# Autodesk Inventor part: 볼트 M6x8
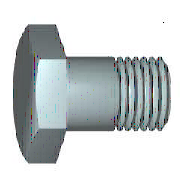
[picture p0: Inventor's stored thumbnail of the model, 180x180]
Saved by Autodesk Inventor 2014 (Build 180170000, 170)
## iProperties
Created: 2012-02
Part Number: 볼트 M6x8
Material: 강철, 연강
Description: 6각 머리 볼트 및 6각 머리 나사
Document SubType Name: Modeling
Standard: KS B 1002
Designer: mduedu
Standards Organization: KS
Language: ko-KR
Size Designation: C  M 6 x 12
Categories: <MemberInstance><Categories><Category DisplayName="조임쇠" InternalName="e4da775c-781d-43d5-af7c-5136215cf5a6" Mnemonic="FSTN"><Category DisplayName="볼트" InternalN
Density: 1 g/cm^3
Appearance: 강철
IsCustomPart: 1
Author: mduedu
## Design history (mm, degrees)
sketch "스케치1"
  geometry: L1 (0, 3)-(8, 3); L2 (8, 3)-(8, 0); L3 (8, 0)-(0, 0); L4 (-2.4, 0)-(14.4, 0) reference; L5 (0, -0.6)-(0, 3.6) reference; L6 (0, 3)-(0, 0)
  constraints: 8 end point, 3 point on line, 1 collinear
  dimensions: "d2" = 6 diameter of L1 L3 (= GD); "d59" = 8 distance between parallel lines of L2 L5 (= NLG)
revolve "본체" sketch "스케치1" stored, may be unused: angle "d12" = 90 deg
sketch "스케치2"
  geometry: L1 (0, 5.774)-(5, 2.887); L2 (5, 2.887)-(5, -2.887); L3 (5, -2.887)-(0, -5.774); L4 (0, -5.774)-(-5, -2.887); L5 (-5, -2.887)-(-5, 2.887); L6 (-5, 2.887)-(0, 5.774); L7 (-7, 0)-(7, 0) reference; L8 (0, 8.083)-(0, -8.083) reference; 2 further points
  constraints: 12 end point, 2 midpoint, 1 coincident, 1 vertical, 11 other
  dimensions: "d11" = 10 distance between parallel lines of L5 L2 (= SW)
extrude "머리" join sketch "스케치2" distance "d3" = 4 (= KOH); taper "d4" = 0 deg
revolve "모따기1" stored, may be unused: angle "d21" = 90 deg
workplane "Work Plane1"
body "Solid1"
feature "스레드" dims "d15" = 9 (= GEL), "d16" = 0
chamfer "모따기2" distance "d6" = 0.61345 (= -0.5 x SPD + 0.5 x GD); stored, may be unused: second distance "d7" = 0.61355 (computed from GUL), angle "d55" = 45 deg
sketch "스케치4"
  geometry: L1 (-3.423, 6)-(-4, 5); L2 (-1.1, 0)-(-0.234, 0); L3 (-4.753, 0)-(0.519, 0) reference; L4 (-4, 6)-(-3.423, 6); L5 (-4, 5)-(-4, 6); L6 (0, 7.2)-(0, -1.2) reference
  constraints: 8 end point, 1 parallel, 1 perpendicular, 1 point on line
  dimensions: "d65" = 10 diameter of L1.end L2 (= SW); "d67" = 30 deg angle of L1 L5 (= ANG1); "d68" = 12 diameter of L4 L2 (= 1.2 x SW); "d69" = 4 distance between parallel lines of L5 L6 (= KOH)
other parameters: "NLG" = 8 [user parameter; used in 1 equation term], "GD" = 6 (= NND) [user parameter; used in 2 equation terms], "BDM" = 6 (= NND) [user parameter], "KOH" = 4 [user parameter; used in 2 equation terms], "GEL" = 9 [user parameter; used in 1 equation term], "SW" = 10 [user parameter; used in 5 equation terms], "SPD" = 4.7731 (= NND - 1.2269 x PTC) [user parameter; used in 1 equation term], "SD2" = 6 (= NND) [user parameter], "SD" = 0 [user parameter], "ANG1" = 30 deg [user parameter; used in 1 equation term], "GAL" = 0.61345 (= 0.61345 x PTC) [user parameter], "GUL" = 0.61345 (= 0.61345 x PTC) [user parameter; used in 1 equation term], "d8" = 0, "RR" = 0.25 [user parameter], "d58" = 0, "RR1" = 0.1 [user parameter], "GD1" = 4.7731 (= THREADDIA - 1.2269 x PTC) [user parameter], "THREADDIA" = 6 [user parameter; used in 1 equation term], "TOA" = 30 deg [user parameter], "PTC" = 1 [user parameter; used in 5 equation terms], "NND" = 6 [user parameter; used in 4 equation terms], "E0" = 11.55 (= 1.155 x SW) [user parameter]
